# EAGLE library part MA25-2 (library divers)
Header 2x25
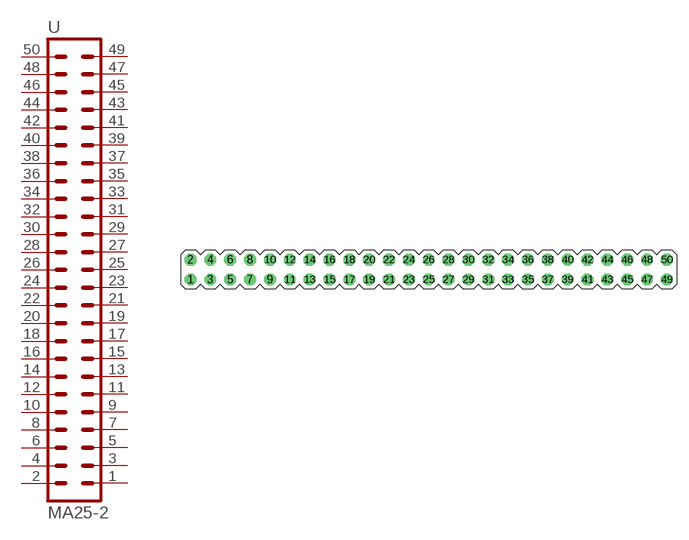
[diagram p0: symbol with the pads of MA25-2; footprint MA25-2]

Designator prefix -

## MA25-2  [MA25-2]
1  1  pas
2  2  pas
3  3  pas
4  4  pas
5  5  pas
6  6  pas
7  7  pas
8  8  pas
9  9  pas
10  10  pas
11  11  pas
12  12  pas
13  13  pas
14  14  pas
15  15  pas
16  16  pas
17  17  pas
18  18  pas
19  19  pas
20  20  pas
21  21  pas
22  22  pas
23  23  pas
24  24  pas
25  25  pas
26  26  pas
27  27  pas
28  28  pas
29  29  pas
30  30  pas
31  31  pas
32  32  pas
33  33  pas
34  34  pas
35  35  pas
36  36  pas
37  37  pas
38  38  pas
39  39  pas
40  40  pas
41  41  pas
42  42  pas
43  43  pas
44  44  pas
45  45  pas
46  46  pas
47  47  pas
48  48  pas
49  49  pas
50  50  pas

## Footprint MA25-2 (pad centres in mm)
PIN HEADER
drill 1.016 octagon: 1 -24.13,-1.27; 2 -24.13,1.27; 3 -21.59,-1.27; 4 -21.59,1.27; 5 -19.05,-1.27; 6 -19.05,1.27; 7 -16.51,-1.27; 8 -16.51,1.27; 9 -13.97,-1.27; 10 -13.97,1.27; 11 -11.43,-1.27; 12 -11.43,1.27; 13 -8.89,-1.27; 14 -8.89,1.27; 15 -6.35,-1.27; 16 -6.35,1.27; 17 -3.81,-1.27; 18 -3.81,1.27; 19 -1.27,-1.27; 20 -1.27,1.27; 21 1.27,-1.27; 22 1.27,1.27; 23 3.81,-1.27; 24 3.81,1.27; 25 6.35,-1.27; 26 6.35,1.27; 27 8.89,-1.27; 28 8.89,1.27; 29 11.43,-1.27; 30 11.43,1.27; 31 13.97,-1.27; 32 13.97,1.27; 33 16.51,-1.27; 34 16.51,1.27; 35 19.05,-1.27; 36 19.05,1.27; 37 21.59,-1.27; 38 21.59,1.27; 39 24.13,-1.27; 40 24.13,1.27; 41 26.67,-1.27; 42 26.67,1.27; 43 29.21,-1.27; 44 29.21,1.27; 45 31.75,-1.27; 46 31.75,1.27; 47 34.29,-1.27; 48 34.29,1.27; 49 36.83,-1.27; 50 36.83,1.27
